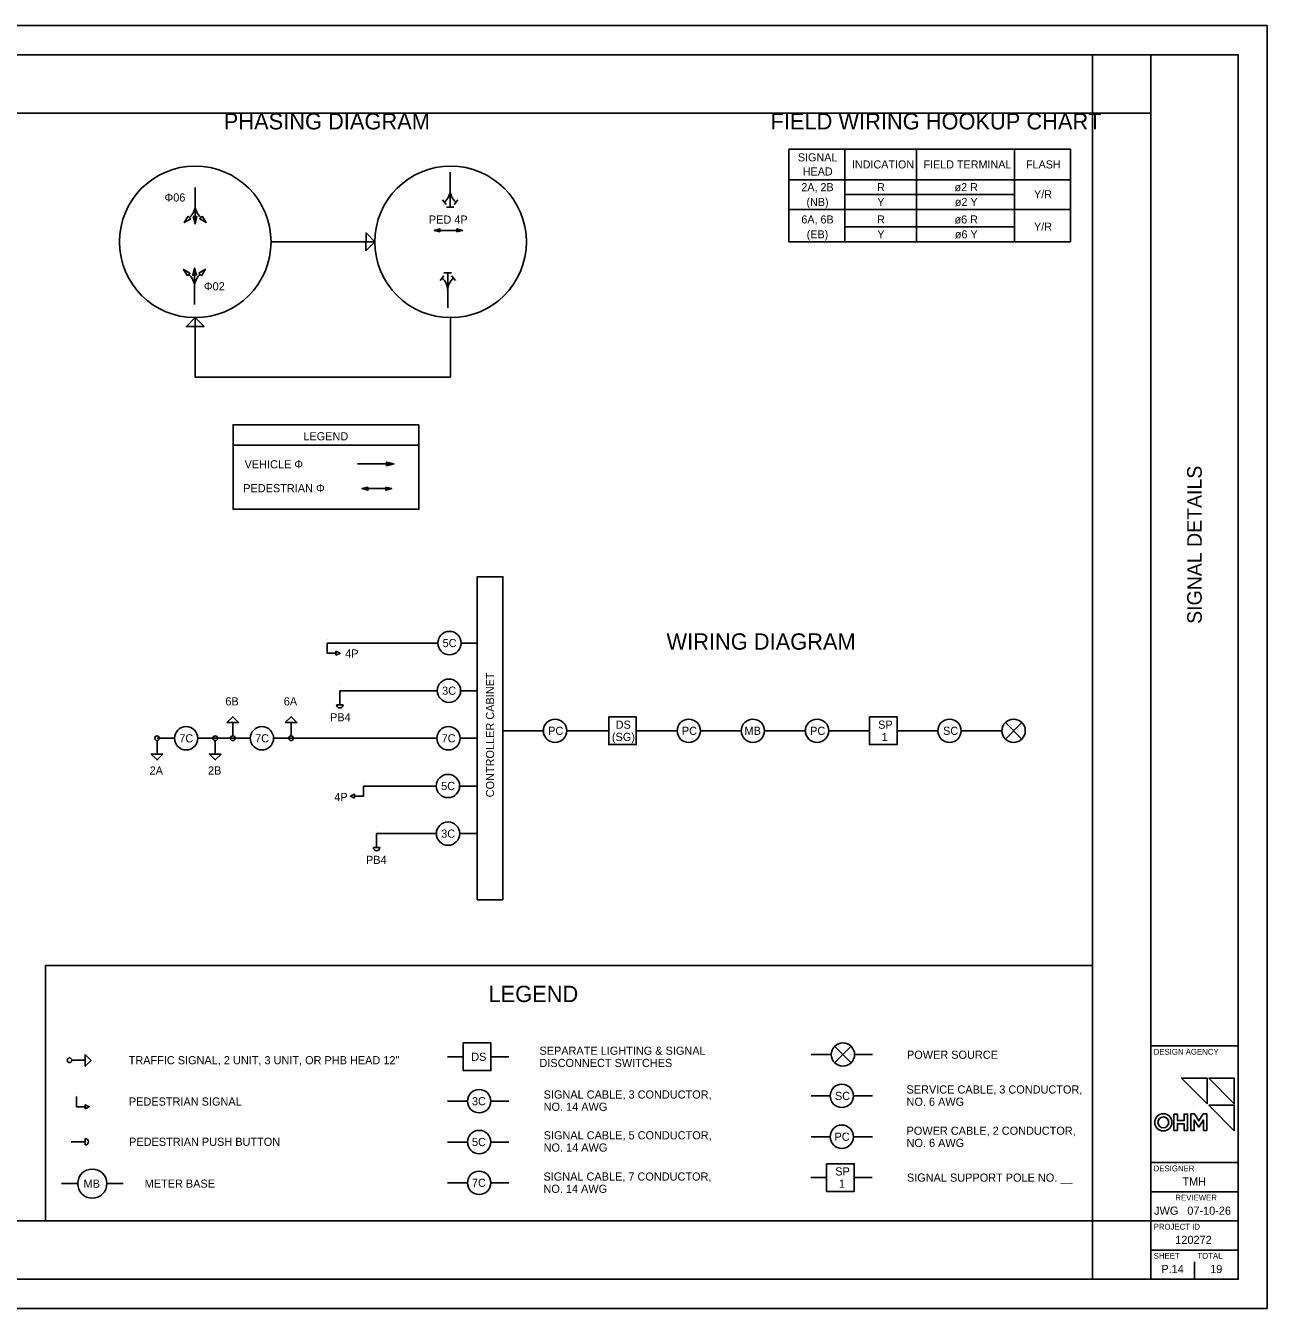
# Model space of a CAD drawing. Extents: x 59.9 to 93.9, y -8.4 to 13.6.
# Drawn here: x 72.65 to 93.95, y -8.39 to 13.61 of the extents above; entities that cross this region are included whole.
import ezdxf

# ---------------------------------------------------------------- set-up
doc = ezdxf.new("R2010")
doc.units = 0
for name, color, linetype in [('Default', 7, 'Continuous'), ('SG_P_Detection', 7, 'Continuous'), ('SG_P_Heads', 7, 'Continuous'), ('SG_P_Text', 7, 'Continuous'), ('SG_P_Wiring', 7, 'Continuous'), ('SH_Border', 7, 'Continuous'), ('SH_Cut_Line', 7, 'Continuous'), ('SH_Data', 7, 'Continuous'), ('SH_Named_Boundary', 7, 'Continuous'), ('TX_P_Misc', 7, 'Continuous')]:
    doc.layers.add(name, color=color, linetype=linetype)

msp = doc.modelspace()

# ---------------------------------------------------------------- linework, layer by layer
at = {"layer": 'Default'}
for points in [[(92.914, -4.446), (92.914, -4.884), (92.478, -4.446)], [(93.381, -4.446), (93.381, -4.884), (92.945, -4.446)], [(92.848, -5.059), (92.912, -5.059), (92.912, -5.342), (92.852, -5.342), (92.852, -5.161), (92.772, -5.285), (92.693, -5.161), (92.693, -5.342), (92.633, -5.342), (92.633, -5.059), (92.697, -5.059), (92.772, -5.178)], [(93.381, -4.91), (93.381, -5.349), (92.945, -4.91)], [(92.346, -5.061), (92.406, -5.061), (92.406, -5.174), (92.519, -5.174), (92.519, -5.061), (92.579, -5.061), (92.579, -5.342), (92.519, -5.342), (92.519, -5.228), (92.406, -5.228), (92.406, -5.342), (92.346, -5.342)]]:
    msp.add_lwpolyline(points, close=True, dxfattribs=at)
at = {"layer": 'SG_P_Detection'}
for p, q in [((78.036, 2.32), (78.036, 2.32)), ((78.036, 2.2), (78.036, 1.96)), ((78.092, 1.96), (77.98, 1.96)), ((78.668, -0.132), (78.668, -0.132)), ((78.668, -0.252), (78.668, -0.492)), ((78.724, -0.492), (78.612, -0.492)), ((73.669, -5.48), (73.669, -5.592)), ((73.309, -5.536), (73.309, -5.536)), ((73.429, -5.536), (73.669, -5.536))]:
    msp.add_line(p, q, dxfattribs=at)
for centre, start, end in [((78.036, 1.96), 180.0002, 359.9998), ((78.668, -0.492), 180.0002, 359.9998), ((73.669, -5.536), 270.0002, 89.9998)]:
    msp.add_arc(centre, 0.056, start, end, dxfattribs=at)
at = {"layer": 'SG_P_Heads'}
for p, q in [((77.82, 3.077), (77.82, 3.077)), ((76.2, 1.423), (76.2, 1.653)), ((77.2, 1.423), (77.2, 1.653)), ((74.9, 1.343), (74.9, 1.113)), ((75.9, 1.343), (75.9, 1.113)), ((78.441, 0.625), (78.441, 0.625)), ((73.44, -4.14), (73.67, -4.14)), ((73.519, -4.701), (73.519, -4.701))]:
    msp.add_line(p, q, dxfattribs=at)
for points in [[(77.82, 3.017), (77.82, 2.842), (77.97, 2.842)], [(78.441, 0.565), (78.441, 0.39), (78.291, 0.39)], [(73.519, -4.761), (73.519, -4.936), (73.669, -4.936)]]:
    msp.add_lwpolyline(points, dxfattribs=at)
for points in [[(77.97, 2.807), (77.97, 2.877), (78.04, 2.842)], [(76.1, 1.652), (76.2, 1.752), (76.3, 1.652)], [(77.1, 1.652), (77.2, 1.752), (77.3, 1.652)], [(75, 1.113), (74.9, 1.013), (74.8, 1.113)], [(76, 1.113), (75.9, 1.013), (75.8, 1.113)], [(78.291, 0.355), (78.291, 0.425), (78.221, 0.39)], [(73.669, -4.041), (73.769, -4.141), (73.669, -4.241)], [(73.669, -4.971), (73.669, -4.901), (73.739, -4.936)]]:
    msp.add_lwpolyline(points, close=True, dxfattribs=at)
for centre in [(74.9, 1.383), (75.9, 1.383), (76.2, 1.383), (77.2, 1.383), (73.4, -4.14)]:
    msp.add_circle(centre, 0.04, dxfattribs=at)
at = {"layer": 'SG_P_Text'}
for p, q in [((85.74, 11.488), (90.57, 11.488)), ((85.74, 11.488), (85.74, 9.898)), ((86.7, 11.488), (86.7, 9.898)), ((87.93, 11.488), (87.93, 9.898)), ((89.61, 11.488), (89.61, 9.898)), ((90.57, 11.488), (90.57, 9.898)), ((79.929, 11.092), (79.929, 10.491)), ((79.929, 11.092), (79.929, 10.786)), ((79.929, 11.092), (79.929, 10.786)), ((75.552, 10.206), (75.552, 10.829)), ((75.552, 10.829), (75.554, 10.523)), ((75.552, 10.829), (75.554, 10.523)), ((85.74, 10.963), (90.572, 10.963)), ((79.862, 10.54), (79.798, 10.62)), ((79.996, 10.54), (80.06, 10.62)), ((86.7, 10.708), (89.61, 10.708)), ((79.865, 10.491), (79.992, 10.491)), ((85.74, 10.453), (90.569, 10.453)), ((86.7, 10.153), (89.61, 10.153)), ((79.655, 10.095), (80.143, 10.095)), ((78.637, 9.898), (76.856, 9.898)), ((85.74, 9.898), (90.57, 9.898)), ((75.545, 9.449), (75.545, 8.826)), ((79.82, 9.316), (79.756, 9.236)), ((79.823, 9.365), (79.95, 9.365)), ((79.887, 8.764), (79.887, 9.365)), ((79.953, 9.316), (80.018, 9.236)), ((75.545, 8.826), (75.544, 9.131)), ((75.545, 8.826), (75.544, 9.131)), ((79.887, 8.764), (79.887, 9.069)), ((79.887, 8.764), (79.887, 9.069)), ((75.556, 8.598), (75.556, 7.579)), ((79.937, 8.598), (79.937, 7.579)), ((79.937, 7.579), (75.556, 7.579)), ((76.203, 6.41), (79.394, 6.41)), ((78.963, 6.09), (78.34, 6.09)), ((78.928, 5.665), (78.415, 5.665)), ((80.393, 3.017), (80.118, 3.017)), ((80.393, 2.2), (80.109, 2.2)), ((89.455, 1.653), (89.738, 1.37)), ((89.455, 1.37), (89.738, 1.653)), ((80.393, 1.383), (80.1, 1.383)), ((80.385, 0.565), (80.091, 0.565)), ((80.386, -0.252), (80.093, -0.252)), ((86.525, -3.899), (86.808, -4.182)), ((86.525, -4.182), (86.808, -3.899)), ((80.155, -4.079), (79.882, -4.079)), ((80.936, -4.079), (80.629, -4.079)), ((86.467, -4.041), (86.121, -4.041)), ((87.175, -4.041), (86.867, -4.041)), ((86.448, -4.75), (86.121, -4.75)), ((87.175, -4.75), (86.848, -4.75)), ((80.227, -4.841), (79.882, -4.841)), ((80.936, -4.841), (80.627, -4.841)), ((86.448, -5.45), (86.121, -5.45)), ((87.175, -5.45), (86.848, -5.45)), ((80.227, -5.541), (79.882, -5.541)), ((80.936, -5.541), (80.627, -5.541)), ((86.388, -6.15), (86.114, -6.15)), ((87.168, -6.15), (86.862, -6.15)), ((73.54, -6.255), (73.263, -6.255)), ((74.317, -6.255), (74.04, -6.255)), ((80.227, -6.241), (79.882, -6.241)), ((80.936, -6.241), (80.627, -6.241))]:
    msp.add_line(p, q, dxfattribs=at)
for points in [[(75.433, 10.338), (75.368, 10.228), (75.478, 10.294)], [(75.521, 10.331), (75.552, 10.206), (75.584, 10.331)], [(75.676, 10.34), (75.742, 10.229), (75.632, 10.295)], [(79.754, 10.071), (79.655, 10.095), (79.754, 10.12)], [(80.044, 10.071), (80.143, 10.095), (80.044, 10.12)], [(78.637, 9.898), (78.486, 10.05), (78.485, 9.746)], [(75.422, 9.315), (75.356, 9.426), (75.466, 9.36)], [(75.577, 9.324), (75.545, 9.449), (75.514, 9.324)], [(75.664, 9.316), (75.73, 9.427), (75.62, 9.36)], [(75.556, 8.598), (75.405, 8.447), (75.708, 8.447)], [(79.394, 6.76), (76.206, 6.76), (76.206, 5.311), (79.394, 5.311)], [(78.838, 6.058), (78.963, 6.09), (78.838, 6.121)], [(78.519, 5.691), (78.415, 5.665), (78.519, 5.639)], [(78.824, 5.691), (78.928, 5.665), (78.824, 5.639)], [(82.649, 1.749), (83.123, 1.749), (83.123, 1.275), (82.649, 1.275)], [(87.123, 1.749), (87.596, 1.749), (87.596, 1.275), (87.123, 1.275)], [(72.987, -2.511), (90.948, -2.511), (90.948, -6.894), (72.987, -6.894)], [(80.155, -3.842), (80.629, -3.842), (80.629, -4.316), (80.155, -4.316)], [(86.388, -5.913), (86.862, -5.913), (86.862, -6.387), (86.388, -6.387)]]:
    msp.add_lwpolyline(points, close=True, dxfattribs=at)
for centre, radius in [((75.556, 9.898), 1.3), ((79.937, 9.898), 1.3), ((79.918, 3.017), 0.2), ((79.909, 2.2), 0.2), ((75.4, 1.383), 0.2), ((76.7, 1.383), 0.2), ((79.9, 1.383), 0.2), ((81.729, 1.512), 0.2), ((84.023, 1.512), 0.2), ((85.123, 1.512), 0.2), ((86.223, 1.512), 0.2), ((88.496, 1.512), 0.2), ((89.596, 1.512), 0.2), ((79.891, 0.565), 0.2), ((79.893, -0.252), 0.2), ((86.667, -4.041), 0.2), ((86.648, -4.75), 0.2), ((80.427, -4.841), 0.2), ((86.648, -5.45), 0.2), ((80.427, -5.541), 0.2), ((73.79, -6.255), 0.25), ((80.427, -6.241), 0.2)]:
    msp.add_circle(centre, radius, dxfattribs=at)
for centre, start, end in [((79.664, 10.786), 308.7993, 0), ((80.194, 10.786), 180, 231.2007), ((75.289, 10.522), 309.0465, 0.2472), ((75.819, 10.525), 180.2472, 231.4479), ((75.279, 9.13), 0.2472, 51.4479), ((75.809, 9.133), 129.0465, 180.2472), ((79.622, 9.069), 360, 51.2007), ((80.152, 9.069), 128.7993, 180)]:
    msp.add_arc(centre, 0.265, start, end, dxfattribs=at)
at = {"layer": 'SG_P_Wiring'}
for p, q in [((79.718, 3.017), (77.82, 3.017)), ((79.709, 2.2), (78.036, 2.2)), ((75.2, 1.383), (74.9, 1.383)), ((75.9, 1.383), (75.6, 1.383)), ((76.5, 1.383), (75.9, 1.383)), ((77.2, 1.383), (76.9, 1.383)), ((79.7, 1.383), (77.2, 1.383)), ((81.529, 1.512), (80.829, 1.512)), ((81.929, 1.512), (82.649, 1.512)), ((83.823, 1.512), (83.123, 1.512)), ((84.223, 1.512), (84.923, 1.512)), ((85.323, 1.512), (86.023, 1.512)), ((86.423, 1.512), (87.123, 1.512)), ((87.596, 1.512), (88.296, 1.512)), ((88.696, 1.512), (89.396, 1.512)), ((79.691, 0.565), (78.441, 0.565)), ((79.693, -0.252), (78.668, -0.252))]:
    msp.add_line(p, q, dxfattribs=at)
msp.add_lwpolyline([(80.833, -1.39), (80.393, -1.39), (80.393, 4.155), (80.833, 4.155)], close=True, dxfattribs=at)
at = {"layer": 'SH_Border'}
for p, q in [((91.948, -7.894), (91.948, 13.106)), ((91.948, -3.894), (93.448, -3.894)), ((91.948, -5.894), (93.448, -5.894)), ((91.948, -6.394), (93.448, -6.394)), ((91.948, -6.894), (93.448, -6.894)), ((91.948, -7.394), (93.448, -7.394))]:
    msp.add_line(p, q, dxfattribs=at)
msp.add_lwpolyline([(61.448, 13.106), (93.448, 13.106), (93.448, -7.894), (61.448, -7.894)], close=True, dxfattribs=at)
at = {"layer": 'SH_Cut_Line'}
msp.add_lwpolyline([(59.948, -8.394), (93.948, -8.394), (93.948, 13.606), (59.948, 13.606)], close=True, dxfattribs=at)
at = {"layer": 'SH_Data'}
for p, q in [((92.698, -4.894), (92.698, -4.894)), ((92.698, -7.894), (92.698, -7.594)), ((92.323, -7.719), (92.323, -7.719))]:
    msp.add_line(p, q, dxfattribs=at)
at = {"layer": 'SH_Named_Boundary'}
for points in [[(91.948, 13.106), (90.948, 13.106), (90.948, 12.106), (91.948, 12.106)], [(62.448, 12.106), (90.948, 12.106), (90.948, -6.894), (62.448, -6.894)], [(91.948, -7.894), (90.948, -7.894), (90.948, -6.894), (91.948, -6.894)]]:
    msp.add_lwpolyline(points, close=True, dxfattribs=at)
at = {"layer": 'TX_P_Misc'}
for p, q in [((92.693, -5.342), (92.693, -5.161)), ((92.693, -5.161), (92.772, -5.285)), ((92.772, -5.285), (92.852, -5.161)), ((92.852, -5.161), (92.852, -5.342))]:
    msp.add_line(p, q, dxfattribs=at)
for points in [[(92.478, -4.446), (92.914, -4.884), (92.914, -4.446), (92.478, -4.446)], [(92.945, -4.446), (93.381, -4.884), (93.381, -4.446), (92.945, -4.446)], [(92.772, -5.178), (92.697, -5.059), (92.633, -5.059), (92.633, -5.342), (92.693, -5.342)], [(92.852, -5.342), (92.912, -5.342), (92.912, -5.059), (92.848, -5.059), (92.772, -5.178)], [(92.945, -4.91), (93.381, -5.349), (93.381, -4.91), (92.945, -4.91)]]:
    msp.add_lwpolyline(points, dxfattribs=at)
msp.add_lwpolyline([(92.346, -5.061), (92.406, -5.061), (92.406, -5.174), (92.519, -5.174), (92.519, -5.061), (92.579, -5.061), (92.579, -5.342), (92.519, -5.342), (92.519, -5.228), (92.406, -5.228), (92.406, -5.342), (92.346, -5.342)], close=True, dxfattribs=at)
for radius in [0.148, 0.148, 0.0927, 0.0927]:
    msp.add_circle((92.164, -5.204), radius, dxfattribs=at)

# ---------------------------------------------------------------- texts
at = {"layer": 'SG_P_Text'}
for s, height, p in [('PHASING DIAGRAM', 0.28, (76.045, 11.826)), ('FIELD WIRING HOOKUP CHART', 0.28, (85.425, 11.826)), ('SIGNAL ', 0.138, (85.895, 11.278)), ('INDICATION', 0.138, (86.822, 11.157)), ('FIELD TERMINAL', 0.138, (88.05, 11.157)), ('FLASH', 0.138, (89.808, 11.157)), ('HEAD', 0.138, (85.979, 11.036)), ('2A, 2B', 0.138, (85.954, 10.767)), ('R', 0.138, (87.253, 10.768)), ('ø2 R', 0.138, (88.583, 10.768)), ('Y/R', 0.138, (89.946, 10.645)), ('Φ06', 0.14, (75.029, 10.589)), ('(NB)', 0.138, (86.042, 10.513)), ('Y', 0.138, (87.257, 10.513)), ('ø2 Y', 0.138, (88.588, 10.513)), ('PED 4P', 0.14, (79.564, 10.21)), ('6A, 6B', 0.138, (85.954, 10.213)), ('R', 0.138, (87.253, 10.213)), ('ø6 R', 0.138, (88.583, 10.213)), ('Y/R', 0.138, (89.946, 10.09)), ('(EB)', 0.138, (86.046, 9.958)), ('Y', 0.138, (87.257, 9.958)), ('ø6 Y', 0.138, (88.588, 9.958)), ('Φ02', 0.14, (75.705, 9.066)), ('LEGEND', 0.14, (77.411, 6.493)), ('VEHICLE Φ', 0.14, (76.403, 6.013)), ('PEDESTRIAN Φ', 0.14, (76.379, 5.603)), ('5C', 0.14, (79.8, 2.947)), ('WIRING DIAGRAM', 0.28, (83.641, 2.903)), ('4P', 0.14, (78.128, 2.767)), ('3C', 0.14, (79.791, 2.13)), ('6B', 0.14, (76.073, 1.947)), ('6A', 0.14, (77.075, 1.947)), ('PB4', 0.14, (77.868, 1.674)), ('PC', 0.14, (81.61, 1.442)), ('DS', 0.14, (82.769, 1.547)), ('PC', 0.14, (83.904, 1.442)), ('MB', 0.14, (84.979, 1.442)), ('PC', 0.14, (86.104, 1.442)), ('SP', 0.14, (87.271, 1.547)), ('SC', 0.14, (88.385, 1.442)), ('7C', 0.14, (75.283, 1.313)), ('7C', 0.14, (76.583, 1.313)), ('7C', 0.14, (79.783, 1.313)), ('(SG)', 0.14, (82.704, 1.337)), ('1', 0.14, (87.333, 1.337)), ('2A', 0.14, (74.773, 0.761)), ('2B', 0.14, (75.775, 0.761)), ('4P', 0.14, (77.941, 0.306)), ('5C', 0.14, (79.774, 0.495)), ('3C', 0.14, (79.775, -0.322)), ('PB4', 0.14, (78.485, -0.772)), ('LEGEND', 0.28, (80.587, -3.141)), ('SEPARATE LIGHTING & SIGNAL', 0.14, (81.461, -4.045)), ('TRAFFIC SIGNAL, 2 UNIT, 3 UNIT, OR PHB HEAD 12"', 0.14, (74.414, -4.208)), ('DS', 0.14, (80.291, -4.149)), ('DISCONNECT SWITCHES', 0.14, (81.461, -4.255)), ('POWER SOURCE', 0.14, (87.766, -4.114)), ('SERVICE CABLE, 3 CONDUCTOR,', 0.14, (87.758, -4.71)), ('PEDESTRIAN SIGNAL', 0.14, (74.418, -4.917)), ('3C', 0.14, (80.303, -4.911)), ('SIGNAL CABLE, 3 CONDUCTOR, ', 0.14, (81.533, -4.796)), ('SC', 0.14, (86.53, -4.82)), ('NO. 6 AWG', 0.14, (87.758, -4.92)), ('NO. 14 AWG', 0.14, (81.533, -5.006)), ('POWER CABLE, 2 CONDUCTOR,', 0.14, (87.759, -5.417)), ('PEDESTRIAN PUSH BUTTON', 0.14, (74.422, -5.607)), ('5C', 0.14, (80.303, -5.611)), ('SIGNAL CABLE, 5 CONDUCTOR, ', 0.14, (81.533, -5.496)), ('PC', 0.14, (86.523, -5.52)), ('NO. 6 AWG', 0.14, (87.759, -5.627)), ('NO. 14 AWG', 0.14, (81.533, -5.706)), ('SIGNAL CABLE, 7 CONDUCTOR, ', 0.14, (81.53, -6.203)), ('SP', 0.14, (86.536, -6.115)), ('SIGNAL SUPPORT POLE NO. __', 0.14, (87.765, -6.222)), ('MB', 0.14, (73.64, -6.325)), ('METER BASE', 0.14, (74.688, -6.325)), ('7C', 0.14, (80.303, -6.311)), ('NO. 14 AWG', 0.14, (81.53, -6.413)), ('1', 0.14, (86.598, -6.325))]:
    msp.add_text(s, height=height, dxfattribs=at).set_placement(p)
msp.add_text('CONTROLLER CABINET', height=0.14, rotation=90, dxfattribs=at).set_placement((80.683, 0.371))
at = {"layer": 'SH_Data'}
msp.add_text('SIGNAL DETAILS', height=0.25, rotation=90, dxfattribs=at).set_placement((92.823, 3.346))
for s, height, p in [('DESIGN AGENCY', 0.1, (91.998, -4.044)), ('DESIGNER', 0.1, (91.998, -6.044)), ('TMH', 0.14, (92.491, -6.289)), ('REVIEWER', 0.1, (92.37, -6.544)), ('JWG', 0.14, (92.005, -6.789)), ('07-10-26', 0.14, (92.575, -6.789)), ('PROJECT ID', 0.1, (91.998, -7.044)), ('120272', 0.14, (92.369, -7.289)), ('SHEET', 0.1, (91.998, -7.544)), ('TOTAL', 0.1, (92.748, -7.544)), ('P.14', 0.14, (92.13, -7.789)), ('19', 0.14, (92.967, -7.789))]:
    msp.add_text(s, height=height, dxfattribs=at).set_placement(p)

doc.saveas('drawing.dxf')
